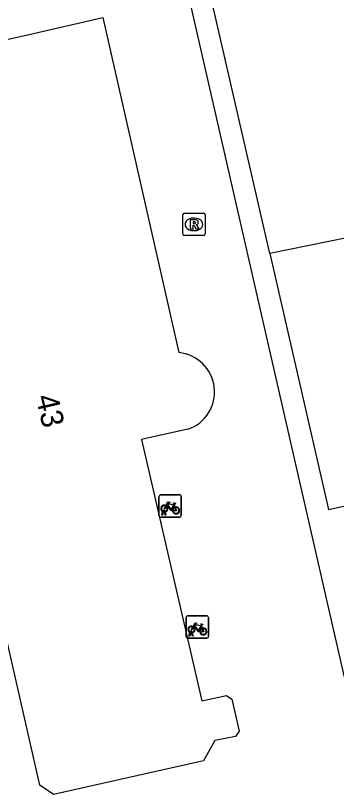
# Model space of a CAD drawing. Extents: x 156664 to 157568, y 383571 to 384421.
# Drawn here: x 156765.52 to 156779.86, y 384056.68 to 384091.54 of the extents above; entities that cross this region are included whole.
import ezdxf

# ---------------------------------------------------------------- set-up
doc = ezdxf.new("R2010")
doc.units = 0
for name, color, linetype in [('IMGEO_Fietsenrek', 7, 'Continuous'), ('IMGEO_Groenvoorziening', 7, 'Continuous'), ('IMGEO_Pand', 7, 'Continuous'), ('IMGEO_Pand_nummerreeks', 7, 'Continuous'), ('IMGEO_Parkeervlak_halfverhard', 7, 'Continuous'), ('IMGEO_Rioolput', 7, 'Continuous'), ('IMGEO_Voetpad_open', 7, 'Continuous')]:
    doc.layers.add(name, color=color, linetype=linetype)

msp = doc.modelspace()

# ---------------------------------------------------------------- linework, layer by layer
at = {"layer": 'IMGEO_Fietsenrek'}
for p, q in [((156771.924, 384069.164), (156771.924, 384070.005)), ((156771.924, 384070.005), (156771.924, 384069.164)), ((156771.999, 384070.089), (156772.84, 384070.089)), ((156772.84, 384070.089), (156771.999, 384070.089)), ((156772.924, 384070.014), (156772.924, 384069.173)), ((156772.924, 384069.173), (156772.924, 384070.014)), ((156772.611, 384069.638), (156772.647, 384069.543)), ((156772.051, 384069.173), (156772.09, 384069.333)), ((156772.085, 384069.173), (156772.051, 384069.173)), ((156772.12, 384069.321), (156772.085, 384069.173)), ((156772.162, 384069.345), (156772.161, 384069.349)), ((156772.203, 384069.173), (156772.169, 384069.315)), ((156772.193, 384069.356), (156772.194, 384069.349)), ((156772.201, 384069.319), (156772.236, 384069.173)), ((156772.236, 384069.173), (156772.203, 384069.173)), ((156772.849, 384069.089), (156772.008, 384069.089)), ((156772.008, 384069.089), (156772.849, 384069.089)), ((156773.215, 384064.675), (156774.056, 384064.675)), ((156774.056, 384064.675), (156773.215, 384064.675)), ((156773.14, 384063.75), (156773.14, 384064.591)), ((156773.14, 384064.591), (156773.14, 384063.75)), ((156774.14, 384064.6), (156774.14, 384063.759)), ((156774.14, 384063.759), (156774.14, 384064.6)), ((156773.378, 384063.931), (156773.377, 384063.935)), ((156773.409, 384063.942), (156773.41, 384063.935)), ((156773.827, 384064.224), (156773.863, 384064.129)), ((156774.065, 384063.675), (156773.224, 384063.675)), ((156773.224, 384063.675), (156774.065, 384063.675)), ((156773.267, 384063.759), (156773.306, 384063.919)), ((156773.301, 384063.759), (156773.267, 384063.759)), ((156773.336, 384063.907), (156773.301, 384063.759)), ((156773.419, 384063.759), (156773.385, 384063.901)), ((156773.417, 384063.905), (156773.452, 384063.759)), ((156773.452, 384063.759), (156773.419, 384063.759))]:
    msp.add_line(p, q, dxfattribs=at)
for points in [[(156772.258, 384069.563), (156772.206, 384069.473), (156772.166, 384069.448), (156772.167, 384069.495), (156772.222, 384069.589)], [(156772.237, 384069.615), (156772.332, 384069.779), (156772.418, 384069.765), (156772.42, 384069.756), (156772.364, 384069.745), (156772.337, 384069.7), (156772.593, 384069.659)], [(156772.533, 384069.371), (156772.483, 384069.371), (156772.292, 384069.622), (156772.273, 384069.59)], [(156772.58, 384069.634), (156772.323, 384069.675), (156772.306, 384069.646), (156772.473, 384069.426), (156772.58, 384069.634)], [(156772.628, 384069.536), (156772.598, 384069.613), (156772.489, 384069.395), (156772.532, 384069.395)], [(156772.562, 384069.395), (156772.682, 384069.394), (156772.638, 384069.508)], [(156772.658, 384069.515), (156772.713, 384069.37), (156772.563, 384069.37)], [(156772.593, 384069.659), (156772.618, 384069.708), (156772.612, 384069.712), (156772.589, 384069.716), (156772.577, 384069.723), (156772.576, 384069.726), (156772.578, 384069.731), (156772.673, 384069.716), (156772.675, 384069.706), (156772.665, 384069.693), (156772.653, 384069.687), (156772.639, 384069.693), (156772.611, 384069.638)], [(156773.453, 384064.201), (156773.548, 384064.365), (156773.634, 384064.351), (156773.636, 384064.342), (156773.58, 384064.331), (156773.553, 384064.286), (156773.809, 384064.245)], [(156773.809, 384064.245), (156773.834, 384064.294), (156773.828, 384064.298), (156773.805, 384064.302), (156773.793, 384064.309), (156773.792, 384064.312), (156773.794, 384064.317), (156773.889, 384064.302), (156773.891, 384064.292), (156773.881, 384064.279), (156773.869, 384064.273), (156773.855, 384064.279), (156773.827, 384064.224)], [(156773.474, 384064.149), (156773.422, 384064.059), (156773.382, 384064.034), (156773.383, 384064.081), (156773.438, 384064.175)], [(156773.749, 384063.957), (156773.699, 384063.957), (156773.508, 384064.208), (156773.489, 384064.176)], [(156773.796, 384064.22), (156773.539, 384064.261), (156773.522, 384064.232), (156773.689, 384064.012), (156773.796, 384064.22)], [(156773.844, 384064.122), (156773.814, 384064.199), (156773.705, 384063.981), (156773.748, 384063.981)], [(156773.778, 384063.981), (156773.898, 384063.98), (156773.854, 384064.094)], [(156773.874, 384064.101), (156773.929, 384063.956), (156773.779, 384063.956)]]:
    msp.add_lwpolyline(points, dxfattribs=at)
for centre, radius, start, end in [((156772.002, 384070.011), 0.0779, 92.4484, 184.2845), ((156772.002, 384070.011), 0.0779, 92.4484, 184.2845), ((156772.846, 384070.011), 0.0779, 2.4484, 94.2845), ((156772.846, 384070.011), 0.0779, 2.4484, 94.2845), ((156772.164, 384069.474), 0.159, 62.6766, 242.1369), ((156772.164, 384069.474), 0.129, 63.3192, 238.903), ((156772.164, 384069.474), 0.129, 283.6043, 43.4302), ((156772.164, 384069.474), 0.159, 283.5766, 46.6042), ((156772.691, 384069.39), 0.159, 113.3408, 178.3217), ((156772.691, 384069.39), 0.159, 187.0065, 105.7708), ((156772.691, 384069.39), 0.129, 113.923, 177.9556), ((156772.691, 384069.39), 0.129, 188.6715, 104.5883), ((156772.002, 384069.167), 0.0779, 182.4484, 274.2845), ((156772.002, 384069.167), 0.0779, 182.4484, 274.2845), ((156772.144, 384069.345), 0.0499, 12.8025, 158.6934), ((156772.164, 384069.474), 0.159, 253.9967, 271.7867), ((156772.144, 384069.345), 0.0174, 12.8025, 163.4502), ((156772.164, 384069.474), 0.129, 253.415, 269.0204), ((156772.846, 384069.167), 0.0779, 272.4484, 4.2845), ((156772.846, 384069.167), 0.0779, 272.4484, 4.2845), ((156773.218, 384064.597), 0.0779, 92.4484, 184.2845), ((156773.218, 384064.597), 0.0779, 92.4484, 184.2845), ((156774.062, 384064.597), 0.0779, 2.4484, 94.2845), ((156774.062, 384064.597), 0.0779, 2.4484, 94.2845), ((156773.38, 384064.06), 0.159, 62.6766, 242.1369), ((156773.38, 384064.06), 0.129, 63.3192, 238.903), ((156773.36, 384063.931), 0.0499, 12.8025, 158.6934), ((156773.36, 384063.931), 0.0174, 12.8025, 163.4502), ((156773.38, 384064.06), 0.129, 253.415, 269.0204), ((156773.38, 384064.06), 0.129, 283.6043, 43.4302), ((156773.38, 384064.06), 0.159, 283.5766, 46.6042), ((156773.907, 384063.976), 0.159, 113.3408, 178.3217), ((156773.907, 384063.976), 0.159, 187.0065, 105.7708), ((156773.907, 384063.976), 0.129, 113.923, 177.9556), ((156773.907, 384063.976), 0.129, 188.6715, 104.5883), ((156773.218, 384063.753), 0.0779, 182.4484, 274.2845), ((156773.218, 384063.753), 0.0779, 182.4484, 274.2845), ((156773.38, 384064.06), 0.159, 253.9967, 271.7867), ((156774.062, 384063.753), 0.0779, 272.4484, 4.2845), ((156774.062, 384063.753), 0.0779, 272.4484, 4.2845)]:
    msp.add_arc(centre, radius, start, end, dxfattribs=at)
at = {"layer": 'IMGEO_Groenvoorziening'}
msp.add_lwpolyline([(156786.796, 384078.796), (156784.912, 384080.733), (156782.691, 384080.927), (156781.286, 384081.792), (156776.877, 384080.891)], dxfattribs=at)
at = {"layer": 'IMGEO_Pand'}
for points in [[(156764.189, 384090.252), (156766.18, 384090.707), (156769.412, 384091.447), (156772.816, 384076.452)], [(156773.221, 384073.025), (156771.138, 384072.57), (156773.845, 384060.867), (156774.95, 384061.11), (156775.18, 384060.942), (156775.519, 384059.511), (156775.347, 384059.272), (156774.431, 384059.099), (156773.925, 384058.189), (156767.214, 384056.681), (156766.598, 384057.097), (156763.157, 384072.189)]]:
    msp.add_lwpolyline(points, dxfattribs=at)
msp.add_arc((156772.649, 384074.695), 1.765, 288.9043, 84.5755, dxfattribs=at)
at = {"layer": 'IMGEO_Parkeervlak_halfverhard'}
for points in [[(156776.877, 384080.891), (156773.122, 384097.252), (156772.186, 384097.041)], [(156776.877, 384080.891), (156779.507, 384069.432), (156783.927, 384070.405), (156785.604, 384063.147)]]:
    msp.add_lwpolyline(points, dxfattribs=at)
at = {"layer": 'IMGEO_Rioolput'}
for p, q in [((156772.991, 384081.768), (156772.991, 384082.62)), ((156773.066, 384082.694), (156773.918, 384082.694)), ((156773.479, 384082.474), (156773.504, 384082.474)), ((156773.992, 384082.62), (156773.992, 384081.768)), ((156773.502, 384081.914), (156773.477, 384081.914)), ((156773.918, 384081.694), (156773.066, 384081.694))]:
    msp.add_line(p, q, dxfattribs=at)
for points in [[(156772.991, 384081.768), (156772.991, 384082.62)], [(156773.066, 384082.694), (156773.918, 384082.694)], [(156773.992, 384082.62), (156773.992, 384081.768)], [(156773.58, 384082.392), (156773.328, 384082.394), (156773.328, 384081.994)], [(156773.328, 384081.994), (156773.452, 384081.994), (156773.452, 384082.156), (156773.463, 384082.156)], [(156773.506, 384082.313), (156773.452, 384082.313), (156773.452, 384082.232)], [(156773.452, 384082.232), (156773.504, 384082.232)], [(156773.51, 384082.127), (156773.581, 384081.994), (156773.721, 384081.994), (156773.656, 384082.12)], [(156773.918, 384081.694), (156773.066, 384081.694)]]:
    msp.add_lwpolyline(points, dxfattribs=at)
for centre, radius, start, end in [((156773.068, 384082.618), 0.0765, 91.552, 178.448), ((156773.068, 384082.618), 0.0765, 91.552, 178.448), ((156773.916, 384082.618), 0.0765, 1.552, 88.448), ((156773.916, 384082.618), 0.0765, 1.552, 88.448), ((156773.462, 384082.103), 0.0533, 26.0293, 88.6989), ((156773.488, 384082.421), 0.19, 274.7715, 282.9687), ((156773.512, 384082.217), 0.0964, 77.0061, 93.1865), ((156773.526, 384082.274), 0.0378, 276.6634, 79.6772), ((156773.579, 384082.282), 0.109, 350.3612, 89.416), ((156773.577, 384082.282), 0.112, 277.5842, 350.9817), ((156773.561, 384082.067), 0.108, 29.5134, 73.7905), ((156773.068, 384081.77), 0.0765, 181.552, 268.448), ((156773.068, 384081.77), 0.0765, 181.552, 268.448), ((156773.916, 384081.77), 0.0765, 271.552, 358.448), ((156773.916, 384081.77), 0.0765, 271.552, 358.448)]:
    msp.add_arc(centre, radius, start, end, dxfattribs=at)
for centre, major_axis, ratio, start_param, end_param in [((156773.478, 384082.194), (-0.387, 0.002), 0.722429, 4.712389, 7.853982), ((156773.503, 384082.194), (-0.39, 0.002), 0.717154, 1.570796, 4.712389)]:
    msp.add_ellipse(centre, major_axis=major_axis, ratio=ratio, start_param=start_param, end_param=end_param, dxfattribs=at)
at = {"layer": 'IMGEO_Voetpad_open'}
msp.add_lwpolyline([(156772.186, 384097.041), (156780.202, 384061.931), (156785.604, 384063.147)], dxfattribs=at)

# ---------------------------------------------------------------- texts
at = {"layer": 'IMGEO_Pand_nummerreeks'}
msp.add_text('43', height=1, rotation=282.9384, dxfattribs=at).set_placement((156766.411, 384074.477))

doc.saveas('drawing.dxf')
